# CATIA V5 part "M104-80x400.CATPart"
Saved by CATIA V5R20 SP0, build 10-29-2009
Part number: M104-80x400
Source: Unknown
Bounding box of the stored display mesh (mm): x -39.842 to 39.842, y -39.842 to 39.842, z 0 to 400
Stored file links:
  C:\Users\Utente\Desktop\IO LAVORO\3D X SITO CF\X SITO\M104\M104-80x400.CATPart
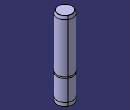
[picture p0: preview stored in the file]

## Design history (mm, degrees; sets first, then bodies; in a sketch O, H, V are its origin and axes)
Body1 (main body)
  Solid1 "PartBody": solid without history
